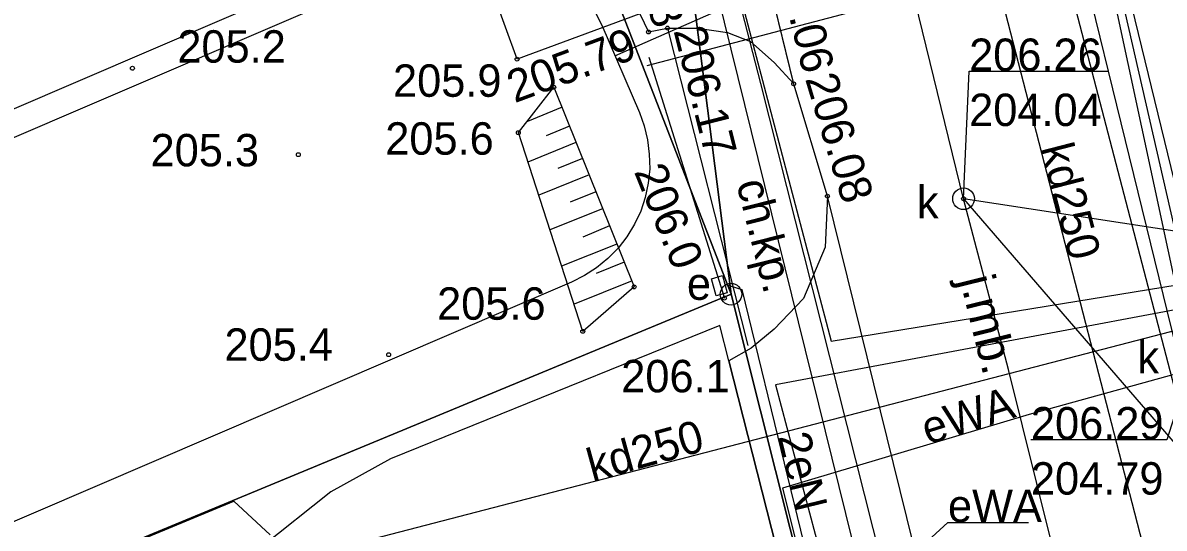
# Model space of a CAD drawing. Extents: x 6512400 to 6513200, y 6022500 to 6022750.
# Drawn here: x 6512839.39 to 6512865.8, y 6022578.54 to 6022590.23 of the extents above; entities that cross this region are included whole.
import ezdxf

# ---------------------------------------------------------------- set-up
doc = ezdxf.new("R2010")
doc.units = 0
for name, color, linetype in [('000 Inne (niezydentyfikowane)', 7, 'Continuous'), ('202-punkt graniczny', 7, 'Continuous'), ('216-obręb ewidencyjny', 7, 'Continuous'), ('217-kontur klasyfikacyjny', 7, 'Continuous'), ('218-kontur użytku gruntowego', 7, 'Continuous'), ('219-działka ewidencyjna', 7, 'Continuous'), ('996-Tekst dodatkowy mały', 7, 'Continuous'), ('chodnik (powierzchnia)', 7, 'Continuous'), ('chodnik (powierzchnia)-Atr17', 7, 'Continuous'), ('jezdnia', 7, 'Continuous'), ('jezdnia (powierzchnia)', 7, 'Continuous'), ('krawężnik', 7, 'Continuous'), ('krawężnik (linia)', 7, 'Continuous'), ('obszar utwardzony', 7, 'Continuous'), ('ogrodzenie trwałe', 7, 'Continuous'), ('pikieta naturalna', 7, 'Continuous'), ('pikieta naturalna-Atr2', 7, 'Continuous'), ('pikieta sztuczna', 7, 'Continuous'), ('pikieta sztuczna-Atr2', 7, 'Continuous'), ('przewód elektroenergetyczny (linia)', 7, 'Continuous'), ('przewód elektroenergetyczny (linia)-Atr1', 7, 'Continuous'), ('przewód kanalizacyjny (linia)', 7, 'Continuous'), ('przewód kanalizacyjny (linia)-Atr1', 7, 'Continuous'), ('przewód kanalizacyjny - projektowany lub w budowie (linia) - ob. projektowany', 7, 'Continuous'), ('przewód telekomunikacyjny (linia)', 7, 'Continuous'), ('przewód wodociągowy (linia)', 7, 'Continuous'), ('punkt o określonej wysokości (sieć kanalizacyjna)', 7, 'Continuous'), ('punkt o określonej wysokości (sieć kanalizacyjna)-Atr2', 7, 'Continuous'), ('punkt o określonej wysokości (sieć kanalizacyjna)-Atr3', 7, 'Continuous'), ('punkt wysokościowy naturalny', 7, 'Continuous'), ('punkt wysokościowy naturalny-Atr2', 7, 'Continuous'), ('punkt wysokościowy sztuczny', 7, 'Continuous'), ('punkt wysokościowy sztuczny-Atr2', 7, 'Continuous'), ('skarpa nieumocniona', 7, 'Continuous'), ('szafa elektroenergetyczna (powierzchnia)', 7, 'Continuous'), ('szafa elektroenergetyczna (powierzchnia)-Atr17', 7, 'Continuous'), ('urządzenie techniczne projektowane lub w budowie (sieć kanalizacyjna) - powierzchnia - ob. projektowany', 7, 'Continuous'), ('właz okrągły - siec kanalizacyjna (punkt)', 7, 'Continuous'), ('właz okrągły - siec kanalizacyjna (punkt)-Atr17', 7, 'Continuous')]:
    doc.layers.add(name, color=color, linetype=linetype)

# ---------------------------------------------------------------- blocks, each defined once
blk = doc.blocks.new('202')
blk.add_circle((0, 0), 0.25)
blk = doc.blocks.new('PW01')
blk.add_circle((0, 0), 0.045)
blk = doc.blocks.new('PW02')
blk.add_circle((0, 0), 0.045)
blk = doc.blocks.new('US22')
blk.add_circle((0, 0), 0.25)

msp = doc.modelspace()

# ---------------------------------------------------------------- linework, layer by layer
at = {"layer": '000 Inne (niezydentyfikowane)'}
for points in [[(6512851.87, 6022588.28), (6512851.07, 6022587.95)], [(6512852.04, 6022587.84), (6512851.5, 6022587.62)], [(6512852.19, 6022587.46), (6512851.08, 6022587.01)], [(6512852.34, 6022587.09), (6512851.77, 6022586.86)], [(6512852.5, 6022586.71), (6512851.33, 6022586.24)], [(6512852.65, 6022586.32), (6512852.06, 6022586.08)], [(6512852.81, 6022585.93), (6512851.59, 6022585.44)], [(6512852.97, 6022585.53), (6512852.35, 6022585.27)], [(6512853.14, 6022585.11), (6512851.86, 6022584.6)], [(6512853.31, 6022584.69), (6512852.66, 6022584.43)], [(6512853.49, 6022584.26), (6512852.15, 6022583.72)]]:
    msp.add_lwpolyline(points, dxfattribs=at)
at = {"layer": '216-obręb ewidencyjny'}
for points in [[(6512836.687, 6022675.173), (6512833.61, 6022675.02), (6512828.67, 6022670.98), (6512801.96, 6022670.34), (6512810.18, 6022663.28), (6512825.37, 6022649.66), (6512838.47, 6022634.29), (6512852.25, 6022608.25), (6512853.17, 6022604.51), (6512855.78, 6022583.95), (6512858.85, 6022571.74), (6512828.23, 6022562.62), (6512818.47, 6022559.72), (6512824.714, 6022553.406)], [(6512780.7, 6022581.02), (6512806.2, 6022572.11), (6512806.62, 6022563.51), (6512811.41, 6022558.95), (6512818.47, 6022559.72), (6512828.23, 6022562.62), (6512858.85, 6022571.74), (6512855.78, 6022583.95), (6512853.17, 6022604.51), (6512852.25, 6022608.25), (6512838.47, 6022634.29), (6512825.37, 6022649.66), (6512810.18, 6022663.28), (6512801.96, 6022670.34), (6512796.96, 6022674.74), (6512790.49, 6022674.74), (6512785.56, 6022674.74), (6512768.24, 6022674.27)]]:
    msp.add_lwpolyline(points, dxfattribs=at)
at = {"layer": '217-kontur klasyfikacyjny'}
for points in [[(6512855.78, 6022583.95), (6512848.55, 6022602.62)], [(6512825.22, 6022571.29), (6512855.78, 6022583.95)]]:
    msp.add_lwpolyline(points, dxfattribs=at)
at = {"layer": '218-kontur użytku gruntowego'}
for points in [[(6512855.78, 6022583.95), (6512853.17, 6022604.51)], [(6512853.17, 6022604.51), (6512855.78, 6022583.95)], [(6512848.55, 6022602.62), (6512855.78, 6022583.95)], [(6512855.78, 6022583.95), (6512848.55, 6022602.62)], [(6512825.22, 6022571.29), (6512855.78, 6022583.95)], [(6512855.78, 6022583.95), (6512825.22, 6022571.29)], [(6512858.85, 6022571.74), (6512855.78, 6022583.95)], [(6512855.78, 6022583.95), (6512858.85, 6022571.74)]]:
    msp.add_lwpolyline(points, dxfattribs=at)
at = {"layer": '219-działka ewidencyjna'}
for points in [[(6512855.78, 6022583.95), (6512853.17, 6022604.51)], [(6512855.78, 6022583.95), (6512848.55, 6022602.62)], [(6512825.22, 6022571.29), (6512855.78, 6022583.95)], [(6512858.85, 6022571.74), (6512855.78, 6022583.95)]]:
    msp.add_lwpolyline(points, dxfattribs=at)
at = {"layer": 'chodnik (powierzchnia)'}
msp.add_lwpolyline([(6512854.31, 6022590.11), (6512856.17, 6022582.76)], dxfattribs=at)
at = {"layer": 'jezdnia'}
msp.add_lwpolyline([(6512857.23, 6022588.82), (6512855.05, 6022597.75), (6512854.94, 6022596.77), (6512854.71, 6022596.06), (6512854.24, 6022595.41), (6512853.71, 6022594.99), (6512853.21, 6022594.73), (6512852.17, 6022594.41), (6512852.27, 6022594.15), (6512853.67, 6022590.44), (6512853.87, 6022590.02), (6512854.31, 6022590.11), (6512855.01, 6022590.11), (6512855.7, 6022590.01), (6512856.23, 6022589.8), (6512856.78, 6022589.31)], close=True, dxfattribs=at)
at = {"layer": 'jezdnia (powierzchnia)'}
for points in [[(6512858.01, 6022586.22), (6512857.96, 6022585.04), (6512857.46, 6022583.85), (6512856.78, 6022583.14), (6512856.25, 6022582.7), (6512855.73, 6022582.41), (6512857.16, 6022576.8), (6512857.52, 6022576.87), (6512858.5, 6022576.75), (6512859.52, 6022576.13), (6512860.31, 6022575.24), (6512860.92, 6022574.44)], [(6512857.37, 6022576.01), (6512857.16, 6022576.8), (6512855.73, 6022582.41), (6512855.52, 6022583.23), (6512847.9, 6022580.14), (6512846.52, 6022579.38), (6512844.89, 6022578.08), (6512844.32, 6022577.3), (6512843.83, 6022576.12), (6512843.75, 6022575.7), (6512844.49, 6022572.59), (6512851.42, 6022574.26), (6512851.6, 6022573.59), (6512851.75, 6022573.46), (6512852.45, 6022574.3), (6512853.58, 6022574.86), (6512856.56, 6022575.84)]]:
    msp.add_lwpolyline(points, close=True, dxfattribs=at)
at = {"layer": 'krawężnik'}
msp.add_lwpolyline([(6512857.23, 6022588.82), (6512855.05, 6022597.75), (6512854.94, 6022596.77), (6512854.71, 6022596.06), (6512854.24, 6022595.41), (6512853.71, 6022594.99), (6512853.21, 6022594.73), (6512852.17, 6022594.41), (6512852.27, 6022594.15), (6512853.67, 6022590.44), (6512853.87, 6022590.02), (6512854.31, 6022590.11), (6512855.01, 6022590.11), (6512855.7, 6022590.01), (6512856.23, 6022589.8), (6512856.78, 6022589.31)], close=True, dxfattribs=at)
at = {"layer": 'krawężnik (linia)'}
for points in [[(6512858.01, 6022586.22), (6512857.23, 6022588.81), (6512855.05, 6022597.75), (6512854.71, 6022599.38), (6512853.35, 6022605.1)], [(6512862.85, 6022595.89), (6512865.97, 6022583.13), (6512868.17, 6022574.3)]]:
    msp.add_lwpolyline(points, dxfattribs=at)
at = {"layer": 'obszar utwardzony'}
msp.add_lwpolyline([(6512853.67, 6022590.44), (6512850.83, 6022589.39), (6512849.48, 6022593.1), (6512852.27, 6022594.15)], close=True, dxfattribs=at)
at = {"layer": 'ogrodzenie trwałe'}
for points in [[(6512853.88, 6022589.44), (6512855.63, 6022583.86)], [(6512818.46, 6022560.27), (6512812.53, 6022565.9), (6512821.8, 6022569.74), (6512835.02, 6022575.32), (6512844.28, 6022579.16), (6512845.12, 6022578.38)]]:
    msp.add_lwpolyline(points, dxfattribs=at)
at = {"layer": 'przewód elektroenergetyczny (linia)'}
for points in [[(6512763.38, 6022676.06), (6512798.79, 6022676.04), (6512803.06, 6022673.02), (6512807.84, 6022668.96), (6512815.24, 6022662.53), (6512819.98, 6022657.77), (6512831.6, 6022645.79), (6512834.59, 6022642.25), (6512837.06, 6022638.75), (6512840.02, 6022634.13), (6512842.26, 6022630.04), (6512846.03, 6022621.35), (6512846.58, 6022618.9), (6512847.6, 6022616.23), (6512852.12, 6022605.09), (6512853.39, 6022601.13), (6512855.57, 6022592.48), (6512858.1, 6022582.86), (6512868.09, 6022584.49), (6512870.03, 6022584.23), (6512871.36, 6022584.34), (6512875.65, 6022585.56), (6512879.74, 6022586.61), (6512881.754, 6022587.357)], [(6512802.27, 6022673.66), (6512807.42, 6022670.09), (6512811.38, 6022666.87), (6512814.66, 6022663.43), (6512826.4, 6022651.65), (6512827.82, 6022650.09), (6512834.03, 6022642.46), (6512842.84, 6022631.19), (6512844.67, 6022626.95), (6512847.57, 6022619.87), (6512849.81, 6022612.67), (6512853.56, 6022600.08), (6512856.46, 6022588.83), (6512861.26, 6022569.82), (6512861.768, 6022567.654)], [(6512861.56, 6022603.29), (6512861.94, 6022603.39), (6512866.18, 6022583.61), (6512856.81, 6022581.85), (6512858.91, 6022573.95), (6512860.571, 6022567.194)], [(6512861.56, 6022603.29), (6512861.94, 6022603.39), (6512866.36, 6022584.08), (6512868.34, 6022583.06), (6512881.4, 6022587.22)], [(6512881.03, 6022586.32), (6512872.09, 6022583.77), (6512862.68, 6022581.17), (6512856.97, 6022579.46), (6512860.103, 6022567.013)], [(6512855.64, 6022584.18), (6512856.03, 6022584.06), (6512858.14, 6022575.39), (6512858.48, 6022574.45)], [(6512866.18, 6022583.61), (6512856.81, 6022581.85), (6512858.91, 6022573.95), (6512860.571, 6022567.194)]]:
    msp.add_lwpolyline(points, dxfattribs=at)
at = {"layer": 'przewód elektroenergetyczny (linia)-Atr1'}
msp.add_lwpolyline([(6512857.85, 6022575.97), (6512860.8, 6022578.67), (6512862.661, 6022578.67)], dxfattribs=at)
at = {"layer": 'przewód kanalizacyjny (linia)'}
for points in [[(6512861.16, 6022586.16), (6512858.32, 6022597.78), (6512853.7, 6022614.72)], [(6512860.63, 6022596.28), (6512867.451, 6022569.839)], [(6512861.16, 6022586.16), (6512870.65, 6022575.16)], [(6512876.14, 6022584.33), (6512872.95, 6022584.35), (6512861.16, 6022586.16)], [(6512865.461, 6022569.074), (6512862.2, 6022582.21), (6512861.16, 6022586.16)], [(6512840.49, 6022576.47), (6512866.73, 6022583.29)]]:
    msp.add_lwpolyline(points, dxfattribs=at)
at = {"layer": 'przewód kanalizacyjny - projektowany lub w budowie (linia) - ob. projektowany'}
msp.add_lwpolyline([(6512853.09, 6022589.47), (6512859.02, 6022592.08)], dxfattribs=at)
at = {"layer": 'przewód telekomunikacyjny (linia)'}
msp.add_lwpolyline([(6512836.6, 6022638.32), (6512844.42, 6022625.21), (6512848.91, 6022613.6), (6512851.86, 6022605.02), (6512853.91, 6022597.19), (6512860.14, 6022571.94), (6512860.33, 6022571.18)], dxfattribs=at)
at = {"layer": 'przewód wodociągowy (linia)'}
for points in [[(6512869.887, 6022570.776), (6512864.23, 6022594.01), (6512863.79, 6022596.02), (6512861.84, 6022602.88)], [(6512869.005, 6022570.437), (6512862.93, 6022593.72)], [(6512863.44, 6022591.77), (6512853.83, 6022589.24)]]:
    msp.add_lwpolyline(points, dxfattribs=at)
at = {"layer": 'punkt o określonej wysokości (sieć kanalizacyjna)-Atr2'}
for points in [[(6512861.16, 6022586.16), (6512861.29, 6022589.11), (6512864.489, 6022589.11)], [(6512866.73, 6022583.29), (6512865.86, 6022580.58), (6512862.719, 6022580.58)]]:
    msp.add_lwpolyline(points, dxfattribs=at)
at = {"layer": 'skarpa nieumocniona'}
msp.add_lwpolyline([(6512851.68, 6022588.74), (6512853.54, 6022584.12), (6512852.35, 6022583.09), (6512850.86, 6022587.69)], close=True, dxfattribs=at)
msp.add_lwpolyline([(6512851.68, 6022588.74), (6512853.54, 6022584.12), (6512852.35, 6022583.09), (6512850.86, 6022587.69)], close=True, dxfattribs=at)
at = {"layer": 'szafa elektroenergetyczna (powierzchnia)'}
msp.add_lwpolyline([(6512855.33, 6022584.31), (6512855.58, 6022584.38), (6512855.69, 6022583.98), (6512855.44, 6022583.91)], close=True, dxfattribs=at)
at = {"layer": 'urządzenie techniczne projektowane lub w budowie (sieć kanalizacyjna) - powierzchnia - ob. projektowany'}
for points in [[(6512848.68, 6022592.32), (6512816.84, 6022578.64)], [(6512817.02, 6022578.07), (6512848.86, 6022591.74)], [(6512852.64, 6022590.48), (6512852.79, 6022590.18), (6512853.66, 6022588.16), (6512853.77, 6022587.85), (6512853.85, 6022587.52), (6512853.89, 6022587.19), (6512853.9, 6022586.85), (6512853.86, 6022586.52), (6512853.79, 6022586.19), (6512853.69, 6022585.87), (6512853.55, 6022585.57), (6512853.37, 6022585.28), (6512853.17, 6022585.02), (6512852.93, 6022584.78), (6512852.67, 6022584.56), (6512852.39, 6022584.38), (6512852.09, 6022584.23), (6512820.25, 6022570.56)]]:
    msp.add_lwpolyline(points, dxfattribs=at)

# ---------------------------------------------------------------- block references
at = {"layer": '202-punkt graniczny'}
msp.add_blockref('202', (6512855.78, 6022583.95), dxfattribs=at)
at = {"layer": 'pikieta naturalna'}
for p in [(6512851.68, 6022588.74), (6512850.86, 6022587.69), (6512845.77, 6022587.18), (6512853.54, 6022584.12), (6512855.63, 6022583.86), (6512852.35, 6022583.09), (6512847.86, 6022582.55)]:
    msp.add_blockref('PW01', p, dxfattribs=at)
at = {"layer": 'pikieta sztuczna'}
for p in [(6512853.87, 6022590.02), (6512854.31, 6022590.11), (6512850.83, 6022589.39), (6512857.23, 6022588.82)]:
    msp.add_blockref('PW01', p, dxfattribs=at)
at = {"layer": 'punkt o określonej wysokości (sieć kanalizacyjna)'}
msp.add_blockref('PW01', (6512861.16, 6022586.16), dxfattribs=at)
at = {"layer": 'punkt wysokościowy naturalny'}
msp.add_blockref('PW01', (6512841.93, 6022589.18), dxfattribs=at)
at = {"layer": 'punkt wysokościowy sztuczny'}
msp.add_blockref('PW02', (6512858.01, 6022586.22), dxfattribs=at)
at = {"layer": 'właz okrągły - siec kanalizacyjna (punkt)'}
msp.add_blockref('US22', (6512861.16, 6022586.16), dxfattribs=at)

# ---------------------------------------------------------------- texts
at = {"layer": '996-Tekst dodatkowy mały'}
msp.add_text('j.mb.', height=0.8, rotation=283.875, dxfattribs=at).set_placement((6512861.07, 6022584.29))
at = {"layer": 'chodnik (powierzchnia)-Atr17'}
msp.add_text('ch.kp.', height=0.75, rotation=284.201, dxfattribs=at).set_placement((6512855.9, 6022586.52))
at = {"layer": 'pikieta naturalna-Atr2'}
for s, p in [('205.9', (6512847.96, 6022588.52)), ('205.6', (6512847.78, 6022587.18)), ('205.3', (6512842.35, 6022586.91)), ('205.6', (6512848.98, 6022583.36)), ('205.4', (6512844.06, 6022582.41)), ('206.1', (6512853.24, 6022581.68))]:
    msp.add_text(s, height=0.75, dxfattribs=at).set_placement(p)
msp.add_text('206.0', height=0.75, rotation=291.93, dxfattribs=at).set_placement((6512853.53, 6022586.79))
at = {"layer": 'pikieta sztuczna-Atr2'}
for s, rotation, p in [('206.18', 290.674, (6512852.947, 6022592.928)), ('206.06', 283.719, (6512856.725, 6022592.001)), ('205.79', 20.29, (6512850.772, 6022588.369)), ('206.17', 284.201, (6512854.446, 6022590.052))]:
    msp.add_text(s, height=0.75, rotation=rotation, dxfattribs=at).set_placement(p)
at = {"layer": 'przewód elektroenergetyczny (linia)-Atr1'}
for s, rotation, p in [('eWA', 17.492, (6512860.33, 6022580.46)), ('2eN', 283.678, (6512856.86, 6022580.66))]:
    msp.add_text(s, height=0.75, rotation=rotation, dxfattribs=at).set_placement(p)
msp.add_text('eWA', height=0.75, dxfattribs=at).set_placement((6512860.8, 6022578.678))
at = {"layer": 'przewód kanalizacyjny (linia)-Atr1'}
for rotation, p in [(284.465, (6512862.94, 6022587.34)), (15.379, (6512852.57, 6022579.61))]:
    msp.add_text('kd250', height=0.75, rotation=rotation, dxfattribs=at).set_placement(p)
at = {"layer": 'punkt o określonej wysokości (sieć kanalizacyjna)-Atr2'}
for s, p in [('206.26', (6512861.29, 6022589.118)), ('206.29', (6512862.719, 6022580.588))]:
    msp.add_text(s, height=0.75, dxfattribs=at).set_placement(p)
at = {"layer": 'punkt o określonej wysokości (sieć kanalizacyjna)-Atr3'}
for s, p in [('204.04', (6512861.29, 6022587.843)), ('204.79', (6512862.719, 6022579.312))]:
    msp.add_text(s, height=0.75, dxfattribs=at).set_placement(p)
at = {"layer": 'punkt wysokościowy naturalny-Atr2'}
msp.add_text('205.2', height=0.75, dxfattribs=at).set_placement((6512842.97, 6022589.31))
at = {"layer": 'punkt wysokościowy sztuczny-Atr2'}
msp.add_text('206.08', height=0.75, rotation=286.76, dxfattribs=at).set_placement((6512857.49, 6022588.94))
at = {"layer": 'szafa elektroenergetyczna (powierzchnia)-Atr17'}
msp.add_text('e', height=0.75, dxfattribs=at).set_placement((6512854.76, 6022583.82))
at = {"layer": 'właz okrągły - siec kanalizacyjna (punkt)-Atr17'}
for p in [(6512860.08, 6022585.71), (6512865.18, 6022582.12)]:
    msp.add_text('k', height=0.75, dxfattribs=at).set_placement(p)

doc.saveas('drawing.dxf')
